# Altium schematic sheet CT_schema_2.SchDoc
size 313 x 200 mm
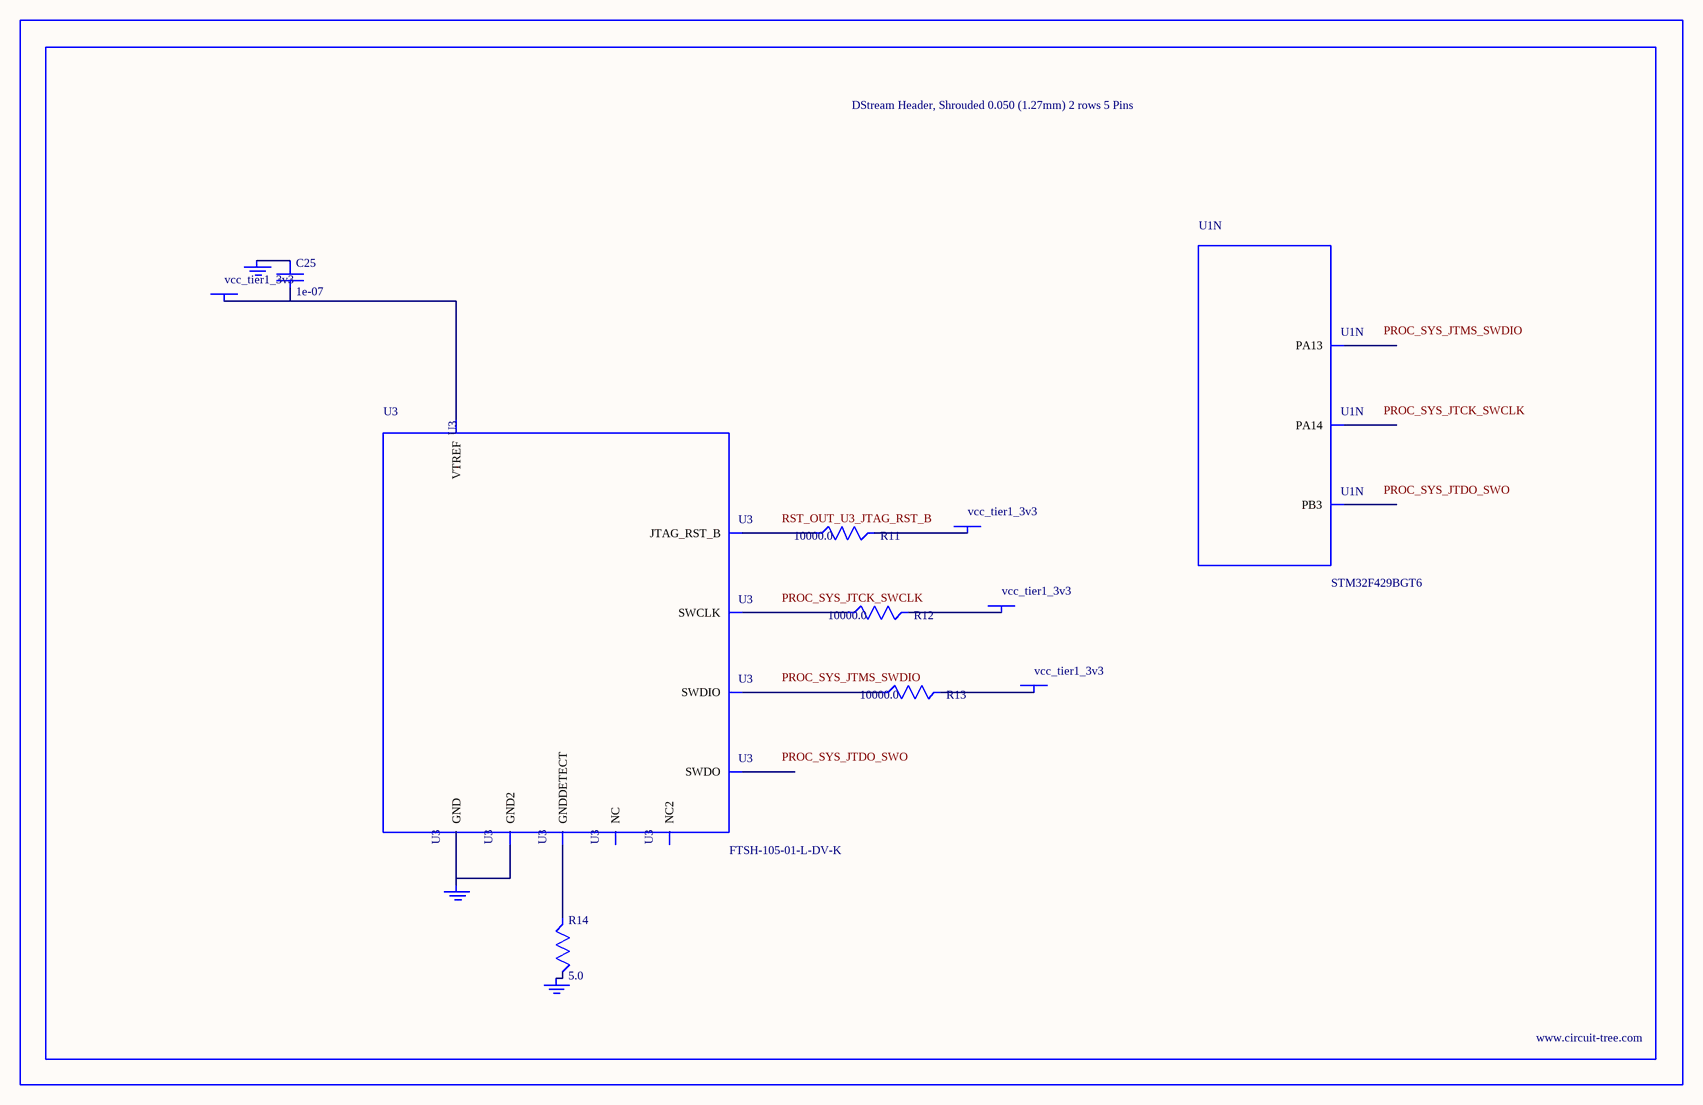
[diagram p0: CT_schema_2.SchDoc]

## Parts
BORDER1  (no value)
C25  1e-07  [C0402]
GND_INSTANCE_1_0  (no value)
GND_INSTANCE_1_1  (no value)
GND_INSTANCE_1_2  (no value)
POWER_INSTANCE_1_0  vcc_tier1_3v3
POWER_INSTANCE_1_1  vcc_tier1_3v3
POWER_INSTANCE_1_2  vcc_tier1_3v3
POWER_INSTANCE_1_3  vcc_tier1_3v3
R11  10000.0  [R0603]
R12  10000.0  [R0603]
R13  10000.0  [R0603]
R14  5.0  [R0603]
U1  STM32F429BGT6  [LQFP208]  (part N of 17)
U3  FTSH-105-01-L-DV-K  [SAMTEC_FTSH-105-01-L-DV-K]

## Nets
NetC25_1: C25.1 GND_INSTANCE_1_0.0(GND)
NetC25_2: C25.2 POWER_INSTANCE_1_0.0(PWR) U3.1(VTREF)
NetGND_INSTANCE_1_1_0: GND_INSTANCE_1_1.0(GND) R14.2
NetGND_INSTANCE_1_2_0: GND_INSTANCE_1_2.0(GND) U3.3(GND) U3.5(GND2)
NetPOWER_INSTANCE_1_1_0: POWER_INSTANCE_1_1.0(PWR) R13.2
NetPOWER_INSTANCE_1_2_0: POWER_INSTANCE_1_2.0(PWR) R12.2
NetPOWER_INSTANCE_1_3_0: POWER_INSTANCE_1_3.0(PWR) R11.2
NetR11_1: R11.1 U3.10(JTAG_RST_B)
NetR12_1: R12.1 U3.4(SWCLK)
NetR13_1: R13.1 U3.2(SWDIO)
NetR14_1: R14.1 U3.9(GNDDETECT)

Not connected (* = marked no-connect by the designer): U1 147(PA13) 159(PA14) 192(PB3); U3 6(SWDO) 7(NC) 8(NC2)

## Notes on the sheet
- Labels drawn without touching a wire or pin: PROC_SYS_JTCK_SWCLK, PROC_SYS_JTDO_SWO, PROC_SYS_JTMS_SWDIO, RST_OUT_U3_JTAG_RST_B

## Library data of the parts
BORDER1 = BORDER_PAGE1
C25 = C0402C104K3RACTU
GND_INSTANCE_1_0-GND_INSTANCE_1_2 = GND
POWER_INSTANCE_1_0-POWER_INSTANCE_1_3 = PWR
R11-R13 = RC0603JR-0710KL
R14 = ERJ-3GEYJ5R1V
